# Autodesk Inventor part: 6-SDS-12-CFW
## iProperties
Shininess: 50.0
Length Units: 11272
Angle Units: 11279
Time Units: 11290
Mass Units: 11286
Length Display Precision: 3
Angle Display Precision: 2
Manager: Cory McConnell
Company: MechaniX Design Solutions
Part Number: 6-SDS-12-CFW
Document SubType Name: Modeling
Designer: CM
Material: CSA G40.21 44W
Created: 2004-01
Manufacturer: Standard
Standards Organization: Custom
Description: LUFF® QD WING PULLEY
Density: 10.49
Volumn: 2.304646865681294
Area: 8.437628188859923
PropertySet Name: Model Information
Control State: 0
Master: False
Checked Out: False
PartAngTol0: 0.5 deg
PartAngTol1: 0.5 deg
PartAngTol2: 0.5 deg
PartAngTol3: 0.5 deg
PartAngTol4: 0.5 deg
PartLinTol1: 0.015 in
PartLinTol2: 0.01 in
PartLinTol3: 0.005 in
PartLinTol4: 0.001 in
Author: CM
Revision Number: 0
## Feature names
1. Revolution2
2. Revolution3
3. Revolution5
4. Mirror2
5. Mirror1
6. Hole4
7. Hole6
8. Circular Pattern2
9. Extrusion8
10. Fillet1
11. Circular Pattern3
12. Revolution6
13. Mirror3
